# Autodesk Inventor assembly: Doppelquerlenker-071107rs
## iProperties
Created: 2007-11
Part Number: Doppelquerlenker-071107rs
Project: 11308
Document SubType Name: Assembly
Designer: rsc
Engineer: Dr.-Ing. Roland Schröder
Manager: Dr.-Ing. Roland Schröder
Company: www.Das-Entwicklungsbuero.de
Author: rsc
Oberflächen: Ra 3,2
Toleranzen: ISO 2768 - m
a: 17.000 oE
b: 10.000 mm
d: 34.000 mm
